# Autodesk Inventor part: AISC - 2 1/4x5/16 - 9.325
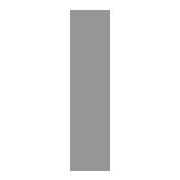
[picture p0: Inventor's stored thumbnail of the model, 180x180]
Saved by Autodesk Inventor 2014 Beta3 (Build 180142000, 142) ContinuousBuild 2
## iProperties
IsCustomPart: 1
Created: 2010-11
Part Number: AISC - 2 1/4x5/16 - 9.325
Material: Steel, Mild
Description: Flat Bar Steel
Document SubType Name: Modeling
Standard: ANSI
Designer: Beta-8540w
Standards Organization: ANSI
Language: en-US
Size Designation: 2 1/4x5/16
Categories: <MemberInstance><Categories><Category DisplayName="Structural Shapes" InternalName="089c4875-fa83-4c05-b084-43b9cc11f5ed" Mnemonic="GRDR"><CategoryParameter Dis
Stock Number: 2 1/4x5/16
Density: 7.86 g/cm^3
Appearance: Steel
_CCFamilyMember: 149
_CCFamilyDisplayName: ANSI AISC (Rectangular) - Flat Bar Steel
_FrameMemberDoc: Frame Member File
_Version: 15.0.0
_GetPNFromCC: 1
G_L: 9.325 in
G_W: 0.313 in
G_H: 2.250 in
Author: Beta-8540w
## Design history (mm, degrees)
node "Start plane"
node "End plane"
node "Driven Length"
  sketch "Sketch3"
    geometry: L1 (0, 0)-(10, 0) reference
    constraints: 2 end point, 1 horizontal
  workplane "Work Plane3"
  sketch "Sketch4"
    geometry: L1 (-2, 0)-(12, 0) reference; L2 (-40.005, 236.864)-(40.005, 236.864) reference
    dimensions: "d9" = 236.86413 distance between parallel lines of L1 L2 (derived)
sketch "Sweep Path"
  geometry: L1 through (25.4, 40.279) direction (1, 0); L2 through (112.121, 127) direction (1, 0); 8 other entities
  constraints: 10 horizontal
node "Orientation Work Plane"
feature "Body" dims "d10" = 0
body "Solid1"
sketch "Sketch"
  geometry: L1 (3.969, -28.575)-(-3.969, -28.575); L2 (-3.969, -28.575)-(-3.969, 28.575); L3 (-3.969, 28.575)-(3.969, 28.575); L4 (3.969, 28.575)-(3.969, -28.575); L5 (-6, 0)-(8, 0); L6 (0, -30)-(0, 40); L7 (0, 54)-(0, -44); L8 (-9.2, 0)-(13.2, 0)
  constraints: 16 end point, 2 collinear, 2 parallel, 1 horizontal, 1 perpendicular
  dimensions: "d0" = 57.15 distance between parallel lines of L3 L1 (= G_W); "d1" = 7.9375 distance between parallel lines of L4 L2 (= G_H); "d4" = 3.96875 distance between parallel lines of L6 L4 (= 0.5 x d1); "d5" = 28.575 distance between parallel lines of L5 L3 (= 0.5 x d0)
other parameters: "G_W" = 57.15 [user parameter; used in 1 equation term], "G_H" = 7.9375 [user parameter; used in 1 equation term], "G_L" = 236.86413 (= d9) [user parameter], "G_OFFSET_START" = 0 [user parameter; used in 1 equation term], "G_OFFSET_END" = 0 [user parameter; used in 1 equation term], "d6" = 0 (computed from G_OFFSET_START), "d7" = 236.86413 (= G_OFFSET_END + B_L), "B_L" = 236.86413 [user parameter; used in 1 equation term], "d8" = 90 deg
